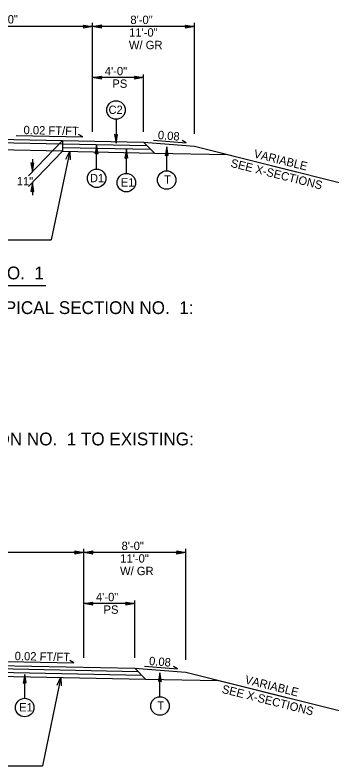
# Model space of a CAD drawing. Extents: x 1901984 to 1902132, y 194049 to 194156.
# Drawn here: x 1902025.5 to 1902050.3, y 194096.6 to 194155.4 of the extents above; entities that cross this region are included whole.
import ezdxf

# ---------------------------------------------------------------- set-up
doc = ezdxf.new("R2010")
doc.units = 0
for name, color, linetype in [('Old_Level_1', 7, 'Continuous'), ('Old_Level_11', 7, 'Continuous'), ('Old_Level_2', 7, 'Continuous'), ('Old_Level_20', 7, 'Continuous'), ('Scratch_Level_3', 7, 'Continuous')]:
    doc.layers.add(name, color=color, linetype=linetype)

# ---------------------------------------------------------------- blocks, each defined once
blk = doc.blocks.new('TERMINATOR')
at = {"layer": 'Scratch_Level_3'}
blk.add_lwpolyline([(-0.469, 0.081), (0, 0), (-0.471, -0.083), (-0.411, 0)], close=True, dxfattribs=at)

msp = doc.modelspace()

# ---------------------------------------------------------------- linework, layer by layer
at = {"layer": 'Old_Level_1'}
for p, q in [((1902031.561, 194146.236), (1902031.561, 194154.776)), ((1902039.554, 194146.076), (1902039.554, 194154.776)), ((1902031.561, 194154.486), (1902019.561, 194154.486)), ((1902039.554, 194154.486), (1902031.561, 194154.486)), ((1902035.561, 194150.486), (1902031.561, 194150.486)), ((1902035.561, 194146.236), (1902035.561, 194150.736)), ((1902020.561, 194145.736), (1902035.561, 194145.436)), ((1902025.564, 194145.968), (1902030.796, 194145.858)), ((1902030.796, 194145.858), (1902030.463, 194146.025)), ((1902019.565, 194145.505), (1902029.22, 194145.312)), ((1902029.22, 194145.562), (1902026.542, 194142.795)), ((1902029.216, 194145.312), (1902035.816, 194145.18)), ((1902029.22, 194145.562), (1902029.22, 194144.729)), ((1902035.561, 194145.436), (1902036.411, 194144.585)), ((1902035.561, 194145.436), (1902037.561, 194145.276)), ((1902036.33, 194145.594), (1902038.91, 194145.388)), ((1902037.561, 194145.276), (1902039.554, 194145.116)), ((1902038.91, 194145.388), (1902038.587, 194145.574)), ((1902039.554, 194145.116), (1902047.554, 194143.116)), ((1902039.554, 194145.116), (1902051.797, 194142.055)), ((1902019.55, 194144.944), (1902029.211, 194144.75)), ((1902029.22, 194144.729), (1902026.542, 194141.962)), ((1902029.776, 194144.718), (1902028.323, 194137.776)), ((1902029.22, 194145.021), (1902036.113, 194144.883)), ((1902029.22, 194144.729), (1902036.411, 194144.585)), ((1902036.411, 194144.585), (1902042.136, 194144.471)), ((1902026.844, 194144.108), (1902026.844, 194143.108)), ((1902026.844, 194142.274), (1902026.844, 194141.274)), ((1902024.414, 194137.776), (1902028.323, 194137.776)), ((1902030.869, 194105.058), (1902030.869, 194113.598)), ((1902038.862, 194104.898), (1902038.862, 194113.598)), ((1902030.869, 194113.308), (1902018.869, 194113.308)), ((1902038.862, 194113.308), (1902030.869, 194113.308)), ((1902034.869, 194109.308), (1902030.869, 194109.308)), ((1902034.869, 194105.058), (1902034.869, 194109.558)), ((1902019.869, 194104.558), (1902034.869, 194104.258)), ((1902024.872, 194104.79), (1902030.105, 194104.68)), ((1902030.105, 194104.68), (1902029.772, 194104.847)), ((1902018.869, 194104.328), (1902035.124, 194104.003)), ((1902018.869, 194104.036), (1902035.422, 194103.705)), ((1902034.869, 194104.258), (1902035.719, 194103.407)), ((1902034.869, 194104.258), (1902036.869, 194104.098)), ((1902035.638, 194104.416), (1902038.218, 194104.21)), ((1902036.869, 194104.098), (1902038.862, 194103.938)), ((1902038.218, 194104.21), (1902037.896, 194104.396)), ((1902038.862, 194103.938), (1902046.862, 194101.938)), ((1902038.862, 194103.938), (1902051.106, 194100.877)), ((1902018.869, 194103.744), (1902035.719, 194103.407)), ((1902029.084, 194103.54), (1902027.632, 194096.598)), ((1902035.719, 194103.407), (1902041.444, 194103.293)), ((1902023.723, 194096.598), (1902027.632, 194096.598))]:
    msp.add_line(p, q, dxfattribs=at)
for points in [[(1902029.482, 194144.109), (1902029.776, 194144.718), (1902029.803, 194144.042)], [(1902028.79, 194102.931), (1902029.084, 194103.54), (1902029.112, 194102.864)]]:
    msp.add_lwpolyline(points, dxfattribs=at)
at = {"layer": 'Old_Level_11'}
for p, q in [((1902033.405, 194147.229), (1902033.405, 194145.355)), ((1902031.882, 194143.331), (1902031.882, 194145.205)), ((1902034.214, 194142.992), (1902034.214, 194144.867)), ((1902037.376, 194143.196), (1902037.376, 194145.07)), ((1902011.269, 194134.201), (1902027.895, 194134.201)), ((1902026.244, 194101.895), (1902026.244, 194103.77)), ((1902036.849, 194102.018), (1902036.849, 194103.893))]:
    msp.add_line(p, q, dxfattribs=at)
for points in [[(1902033.289, 194146.027), (1902033.405, 194145.355), (1902033.524, 194146.03), (1902033.405, 194145.944)], [(1902031.997, 194144.534), (1902031.882, 194145.205), (1902031.762, 194144.53), (1902031.882, 194144.616)], [(1902034.329, 194144.195), (1902034.214, 194144.867), (1902034.094, 194144.191), (1902034.214, 194144.277)], [(1902037.491, 194144.399), (1902037.376, 194145.07), (1902037.256, 194144.395), (1902037.376, 194144.481)], [(1902026.36, 194103.098), (1902026.244, 194103.77), (1902026.125, 194103.094), (1902026.244, 194103.18)], [(1902036.964, 194103.221), (1902036.849, 194103.893), (1902036.729, 194103.217), (1902036.849, 194103.303)]]:
    msp.add_lwpolyline(points, close=True, dxfattribs=at)
for centre in [(1902033.405, 194147.954), (1902031.882, 194142.606), (1902034.214, 194142.267), (1902037.376, 194142.471), (1902026.244, 194101.17), (1902036.849, 194101.293)]:
    msp.add_circle(centre, 0.725, dxfattribs=at)

# ---------------------------------------------------------------- block references
at = {"layer": 'Old_Level_1', "xscale": 1.5, "yscale": 1.5}
for p in [(1902031.561, 194154.486), (1902039.554, 194154.486), (1902035.561, 194150.486), (1902030.869, 194113.308), (1902038.862, 194113.308), (1902034.869, 194109.308)]:
    msp.add_blockref('TERMINATOR', p, dxfattribs=at)
at = {"layer": 'Old_Level_1', "xscale": 1.5}
for p, yscale, rotation in [((1902031.561, 194154.486), 1.5, 180), ((1902031.561, 194150.486), 1.5, 180), ((1902026.844, 194143.108), -1.5, -90), ((1902026.844, 194142.274), -1.5, 90), ((1902030.869, 194113.308), 1.5, 180), ((1902030.869, 194109.308), 1.5, 180)]:
    msp.add_blockref('TERMINATOR', p, dxfattribs=dict(at, yscale=yscale, rotation=rotation))

# ---------------------------------------------------------------- texts
at = {"layer": 'Old_Level_1'}
for s, p in [('12\'-0" ', (1902023.479, 194154.724)), ('8\'-0"', (1902034.53, 194154.683)), ('11\'-0"', (1902034.428, 194153.699)), ('W/ GR', (1902034.411, 194152.715)), ('4\'-0"', (1902032.525, 194150.674)), ('PS', (1902033.116, 194149.69)), ('8\'-0"', (1902033.839, 194113.505)), ('11\'-0"', (1902033.736, 194112.521)), ('W/ GR', (1902033.719, 194111.537)), ('4\'-0"', (1902031.833, 194109.496)), ('PS', (1902032.424, 194108.512))]:
    msp.add_text(s, height=0.656, dxfattribs=at).set_placement(p)
for s, p in [('VARIABLE', (1902044.15, 194144.247)), ('SEE X-SECTIONS', (1902042.342, 194143.508)), ('VARIABLE', (1902043.458, 194103.069)), ('SEE X-SECTIONS', (1902041.65, 194102.33))]:
    msp.add_text(s, height=0.656, rotation=345.96376, dxfattribs=at).set_placement(p)
at = {"layer": 'Old_Level_11'}
for s, p in [('TYPICAL SECTION NO.  1', (1902011.625, 194134.695)), ('TRANSITION FROM EXISTING TO TYPICAL SECTION NO.  1:', (1902001.355, 194131.979)), ('TRANSITION FROM TYPICAL SECTION NO.  1 TO EXISTING:', (1902001.379, 194121.697))]:
    msp.add_text(s, height=1, dxfattribs=at).set_placement(p)
at = {"layer": 'Old_Level_2'}
for s, rotation, p in [('0.02 FT/FT', 358.80842, (1902026.148, 194146.066)), ('0.08', 355.42608, (1902036.662, 194145.685)), ('0.02 FT/FT', 358.80842, (1902025.456, 194104.888)), ('0.08', 355.42608, (1902035.971, 194104.507))]:
    msp.add_text(s, height=0.656, rotation=rotation, dxfattribs=at).set_placement(p)
at = {"layer": 'Old_Level_20'}
for s, height, p in [('C2', 0.6491, (1902032.816, 194147.648)), ('D1', 0.6491, (1902031.36, 194142.302)), ('T', 0.649, (1902037.165, 194142.178)), ('11"', 0.6491, (1902025.629, 194142.063)), ('E1', 0.6491, (1902033.78, 194141.963)), ('T', 0.649, (1902036.638, 194101)), ('E1', 0.6491, (1902025.811, 194100.867))]:
    msp.add_text(s, height=height, dxfattribs=at).set_placement(p)

doc.saveas('drawing.dxf')
